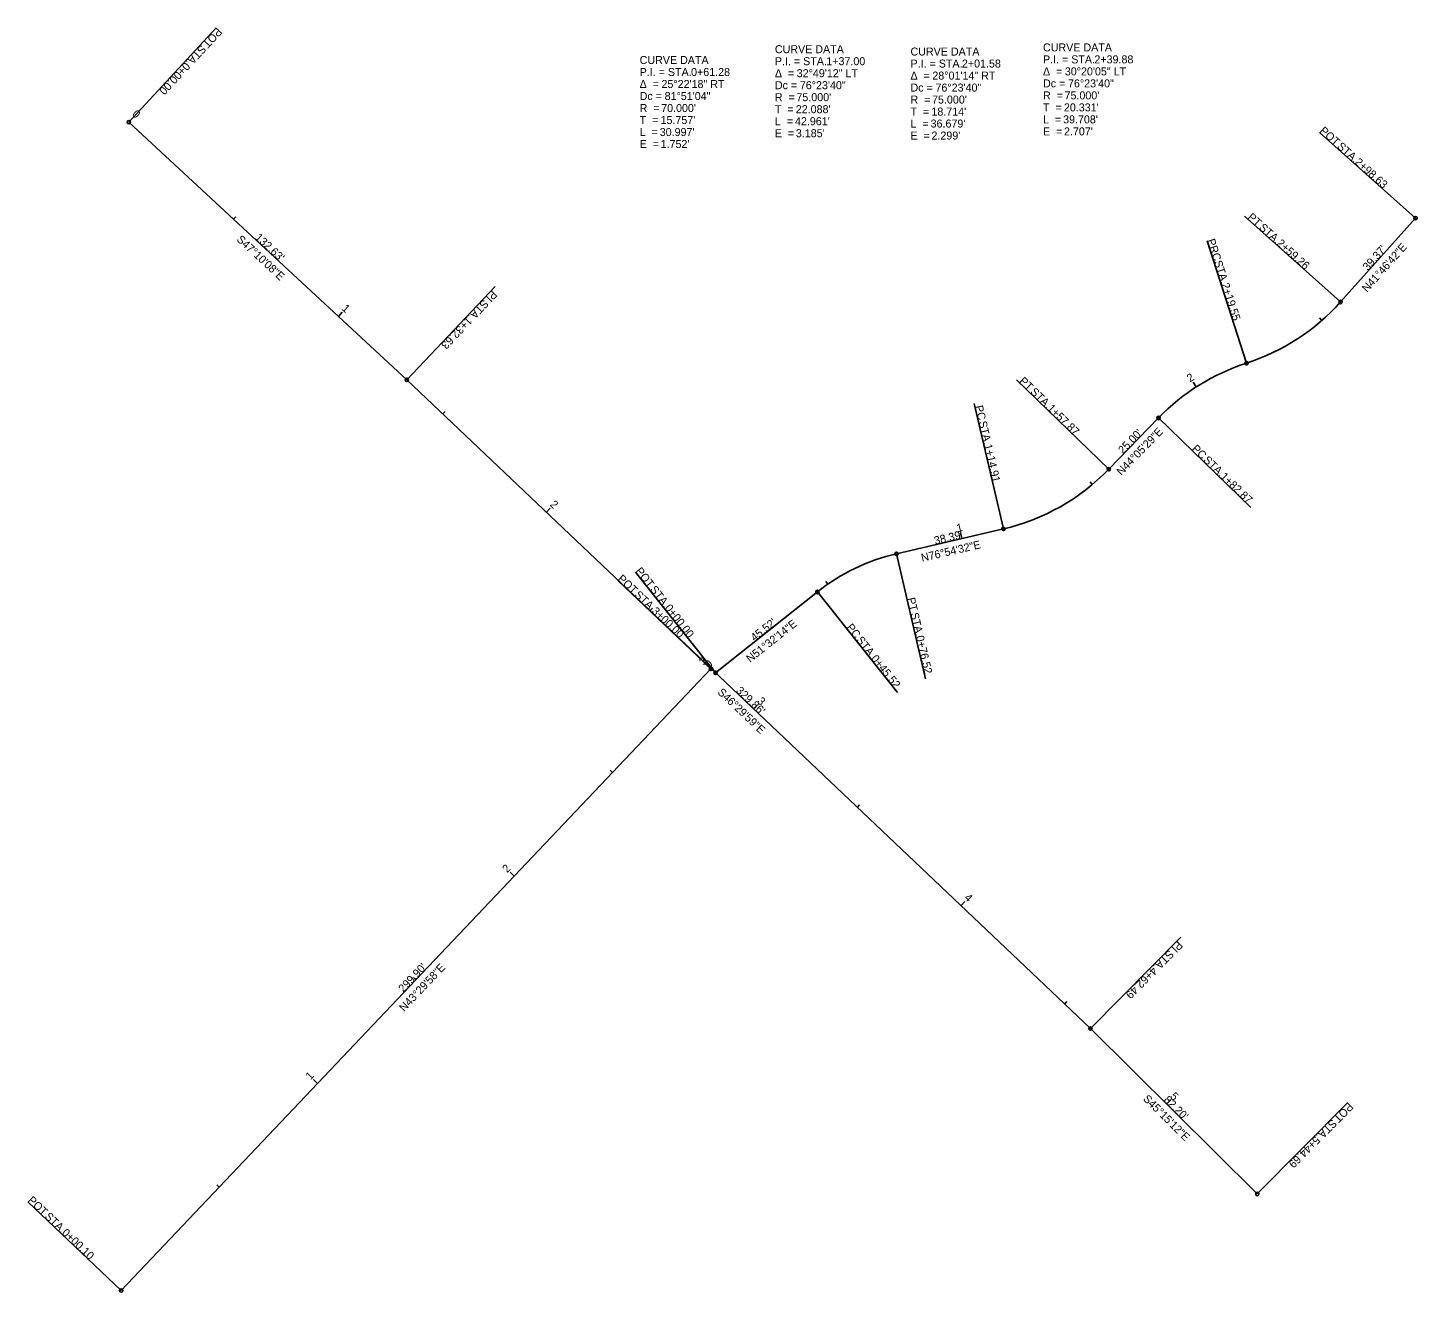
# Model space of a CAD drawing. Extents: x 1481215 to 1481995, y 378012 to 378683.
# Drawn here: x 1481214.6 to 1481700.9, y 378012.5 to 378455 of the extents above; entities that cross this region are included whole.
import ezdxf

# ---------------------------------------------------------------- set-up
doc = ezdxf.new("R2010")
doc.units = 0
for name, color, linetype in [('DT_X_Break_Line', 7, 'Continuous'), ('DT_X_Contour_Major', 7, 'Continuous'), ('DT_X_Island', 7, 'Continuous'), ('DT_X_Spot_Elev', 7, 'Continuous'), ('DT_X_Triangles', 7, 'Continuous'), ('DT_X_Void', 7, 'Continuous')]:
    doc.layers.add(name, color=color, linetype=linetype)

msp = doc.modelspace()

# ---------------------------------------------------------------- linework, layer by layer
at = {"layer": 'DT_X_Break_Line'}
for p, q in [((1481250.01, 378421.95), (1481251.37, 378423.41)), ((1481286.68, 378387.96), (1481287.5, 378388.84)), ((1481323.35, 378353.96), (1481324.71, 378355.43)), ((1481667.5, 378352.51), (1481666.71, 378353.42)), ((1481623.57, 378329.26), (1481622.48, 378330.94)), ((1481359.88, 378319.82), (1481360.7, 378320.69)), ((1481587.19, 378295.11), (1481586.42, 378296.03)), ((1481396.15, 378285.41), (1481397.52, 378286.86)), ((1481541.55, 378276.22), (1481541.1, 378278.17)), ((1481494.59, 378260.21), (1481493.9, 378261.19)), ((1481432.41, 378250.99), (1481433.24, 378251.86)), ((1481453.74, 378230.61), (1481452.29, 378231.99)), ((1481455.35, 378229.22), (1481454.11, 378230.79)), ((1481468.68, 378216.57), (1481470.06, 378218.02)), ((1481419.33, 378194.34), (1481418.46, 378195.17)), ((1481504.95, 378182.15), (1481505.78, 378183.02)), ((1481384.91, 378158.07), (1481383.46, 378159.45)), ((1481541.22, 378147.73), (1481542.6, 378149.18)), ((1481350.49, 378121.8), (1481349.62, 378122.63)), ((1481577.49, 378113.32), (1481578.31, 378114.19)), ((1481316.07, 378085.54), (1481314.62, 378086.91)), ((1481613.19, 378078.31), (1481614.6, 378079.73)), ((1481281.66, 378049.27), (1481280.79, 378050.09))]:
    msp.add_line(p, q, dxfattribs=at)
at = {"layer": 'DT_X_Spot_Elev'}
for p, q in [((1481250.01, 378421.95), (1481280.61, 378454.95)), ((1481700.31, 378388.38), (1481666.75, 378418.36)), ((1481674.08, 378359.02), (1481640.52, 378389)), ((1481641.18, 378337.61), (1481627.36, 378380.44)), ((1481347.28, 378331.78), (1481378.26, 378364.42)), ((1481592.96, 378300.47), (1481560.64, 378331.78)), ((1481556.08, 378279.6), (1481545.88, 378323.43)), ((1481610.35, 378318.42), (1481642.67, 378287.11)), ((1481518.68, 378270.9), (1481528.87, 378227.07)), ((1481455.35, 378229.22), (1481427.36, 378264.46)), ((1481453.74, 378230.61), (1481421.1, 378261.59)), ((1481490.99, 378257.53), (1481518.98, 378222.3)), ((1481586.55, 378104.72), (1481618.23, 378136.68)), ((1481644.93, 378046.85), (1481676.61, 378078.81)), ((1481247.31, 378013.07), (1481214.66, 378044.04))]:
    msp.add_line(p, q, dxfattribs=at)
for centre in [(1481250.01, 378421.95), (1481700.31, 378388.38), (1481674.08, 378359.02), (1481641.18, 378337.61), (1481347.28, 378331.78), (1481610.35, 378318.42), (1481592.96, 378300.47), (1481556.08, 378279.6), (1481518.68, 378270.9), (1481490.99, 378257.53), (1481453.74, 378230.61), (1481455.35, 378229.22), (1481586.55, 378104.72), (1481644.93, 378046.85), (1481247.31, 378013.07)]:
    msp.add_circle(centre, 0.6, dxfattribs=at)
at = {"layer": 'DT_X_Triangles'}
for p, q in [((1481250.01, 378421.95), (1481347.28, 378331.78)), ((1481674.08, 378359.02), (1481700.31, 378388.38)), ((1481347.28, 378331.78), (1481586.55, 378104.72)), ((1481592.96, 378300.47), (1481610.35, 378318.42)), ((1481518.68, 378270.9), (1481556.08, 378279.6)), ((1481455.35, 378229.22), (1481490.99, 378257.53)), ((1481247.31, 378013.07), (1481453.74, 378230.61)), ((1481586.55, 378104.72), (1481644.93, 378046.85))]:
    msp.add_line(p, q, dxfattribs=at)
for centre, radius, start, end in [((1481618.15, 378408.99), 75, 287.8864, 318.2211), ((1481664.22, 378266.24), 75, 107.8883, 135.909), ((1481539.09, 378352.65), 75, 283.0911, 315.9112), ((1481534.53, 378202.72), 70, 103.0911, 128.4628)]:
    msp.add_arc(centre, radius, start, end, dxfattribs=at)

# ---------------------------------------------------------------- texts
at = {"layer": 'DT_X_Break_Line'}
for s, rotation, p in [('0', 317.169, (1481250.95, 378424.48)), ('1', 317.169, (1481324.32, 378356.47)), ('2', 32.823, (1481621.39, 378330.84)), ('2', 316.4996, (1481397.16, 378287.89)), ('1', 13.0911, (1481540.02, 378278.43)), ('3', 46.5006, (1481451.27, 378231.63)), ('0', 38.4628, (1481452.99, 378230.54)), ('3', 316.4996, (1481469.71, 378219.05)), ('2', 46.5006, (1481382.42, 378159.09)), ('4', 316.4996, (1481542.18, 378150.27)), ('1', 46.5006, (1481313.58, 378086.54)), ('5', 315.2533, (1481614.26, 378080.77))]:
    msp.add_text(s, height=2.8, rotation=rotation, dxfattribs=at).set_placement(p)
at = {"layer": 'DT_X_Contour_Major'}
for s, rotation, p in [('S47°10\'08"E', 317.169, (1481287.53, 378380.62)), ('N41°46\'42"E', 48.2217, (1481683.36, 378362.21)), ('N44°05\'29"E', 45.9086, (1481597.37, 378298.12)), ('N76°54\'32"E', 13.0911, (1481527.64, 378268.06)), ('N51°32\'14"E', 38.4628, (1481467.45, 378232.7)), ('S46°29\'59"E', 316.4996, (1481455.84, 378222.14)), ('N43°29\'58"E', 46.5006, (1481346.35, 378110.47)), ('S45°15\'12"E', 315.2533, (1481604.76, 378079.91))]:
    msp.add_text(s, height=2.8, rotation=rotation, dxfattribs=at).set_placement(p)
at = {"layer": 'DT_X_Island'}
for s, p in [('CURVE DATA', (1481476.11, 378446.08)), ('CURVE DATA', (1481523.57, 378445.25)), ('CURVE DATA', (1481569.94, 378446.71)), ('CURVE DATA', (1481428.78, 378442.29)), ('P.I. = STA. ', (1481476.11, 378441.88)), ('1+37.00', (1481494.1, 378441.88)), ('P.I. = STA. ', (1481523.57, 378441.05)), ('2+01.58', (1481541.56, 378441.05)), ('P.I. = STA. ', (1481569.94, 378442.51)), ('2+39.88', (1481587.93, 378442.51)), ('P.I. = STA. ', (1481428.78, 378438.09)), ('0+61.28', (1481446.77, 378438.09)), ('Δ  = ', (1481476.11, 378437.68)), ('32°49\'12" LT', (1481483.75, 378437.68)), ('Δ  = ', (1481523.57, 378436.85)), ('28°01\'14" RT', (1481531.22, 378436.85)), ('Δ  = ', (1481569.94, 378438.31)), ('30°20\'05" LT', (1481577.59, 378438.31)), ('Δ  = ', (1481428.78, 378433.89)), ('25°22\'18" RT', (1481436.42, 378433.89)), ('Dc = ', (1481476.11, 378433.48)), ('76°23\'40"', (1481484.85, 378433.48)), ('Dc = ', (1481523.57, 378432.65)), ('76°23\'40"', (1481532.31, 378432.65)), ('Dc = ', (1481569.94, 378434.11)), ('76°23\'40"', (1481578.69, 378434.11)), ('Dc = ', (1481428.78, 378429.69)), ('R  = ', (1481428.78, 378425.49)), ("70.000'", (1481436.31, 378425.49)), ('81°51\'04"', (1481437.52, 378429.69)), ('R  = ', (1481476.11, 378429.28)), ("75.000'", (1481483.64, 378429.28)), ('R  = ', (1481523.57, 378428.45)), ("75.000'", (1481531.11, 378428.45)), ('T  = ', (1481569.94, 378425.71)), ('R  = ', (1481569.94, 378429.91)), ("20.331'", (1481577.26, 378425.71)), ("75.000'", (1481577.48, 378429.91)), ('T  = ', (1481428.78, 378421.29)), ("15.757'", (1481436.09, 378421.29)), ('T  = ', (1481476.11, 378425.08)), ('L  = ', (1481476.11, 378420.88)), ("42.961'", (1481483.14, 378420.88)), ("22.088'", (1481483.42, 378425.08)), ('T  = ', (1481523.57, 378424.25)), ("18.714'", (1481530.89, 378424.25)), ('L  = ', (1481569.94, 378421.51)), ("39.708'", (1481576.98, 378421.51)), ('L  = ', (1481428.78, 378417.09)), ("30.997'", (1481435.81, 378417.09)), ('E  = ', (1481476.11, 378416.68)), ("3.185'", (1481483.45, 378416.68)), ('L  = ', (1481523.57, 378420.05)), ('E  = ', (1481523.57, 378415.85)), ("36.679'", (1481530.61, 378420.05)), ("2.299'", (1481530.91, 378415.85)), ('E  = ', (1481569.94, 378417.31)), ("2.707'", (1481577.29, 378417.31)), ('E  = ', (1481428.78, 378412.89)), ("1.752'", (1481436.12, 378412.89))]:
    msp.add_text(s, height=2.8, dxfattribs=at).set_placement(p)
at = {"layer": 'DT_X_Spot_Elev'}
for s, rotation, p in [('POT', 227.169, (1481280.88, 378455.19)), (' STA. ', 227.169, (1481276.03, 378449.96)), ('0+00.00', 227.169, (1481269.7, 378443.13)), ('POT', 318.2217, (1481666.55, 378418.58)), (' STA. ', 318.2217, (1481671.87, 378413.83)), ('2+98.63', 318.2217, (1481678.82, 378407.62)), ('PT', 318.2217, (1481641.31, 378388.34)), (' STA. ', 318.2217, (1481644.56, 378385.44)), ('PRC', 287.8864, (1481627.34, 378380.63)), ('2+59.26', 318.2217, (1481651.51, 378379.23)), (' STA. ', 287.8864, (1481629.46, 378374.06)), ('2+19.55', 287.8864, (1481632.32, 378365.19)), (' STA. ', 226.4996, (1481374.89, 378360.82)), ('PI', 226.4996, (1481377.17, 378363.23)), ('1+32.63', 226.4996, (1481368.47, 378354.06)), ('PT', 315.9086, (1481561.41, 378331.08)), (' STA. ', 315.9086, (1481564.54, 378328.05)), ('PC', 283.0911, (1481546.13, 378322.52)), ('1+57.87', 315.9086, (1481571.24, 378321.56)), (' STA. ', 283.0911, (1481547.17, 378318.04)), ('1+14.91', 283.0911, (1481549.29, 378308.96)), ('PC', 315.909, (1481621.81, 378307.37)), (' STA. ', 315.909, (1481625.12, 378304.17)), ('1+82.87', 315.909, (1481631.81, 378297.68)), ('POT', 316.5006, (1481420.86, 378261.87)), ('POT', 308.4628, (1481427.16, 378264.77)), (' STA. ', 316.5006, (1481426.03, 378256.96)), (' STA. ', 308.4628, (1481431.6, 378259.18)), ('0+00.00', 308.4628, (1481437.4, 378251.88)), ('PT', 283.0911, (1481522.36, 378255.25)), ('3+00.00', 316.5006, (1481432.8, 378250.54)), (' STA. ', 283.0911, (1481523.34, 378251.01)), ('PC', 308.4628, (1481500.95, 378245.07)), (' STA. ', 308.4628, (1481503.81, 378241.46)), ('0+76.52', 283.0911, (1481525.45, 378241.93)), ('0+45.52', 308.4628, (1481509.61, 378234.16)), (' STA. ', 225.2533, (1481614.81, 378133.17)), ('PI', 225.2533, (1481617.14, 378135.53)), ('4+62.49', 225.2533, (1481608.25, 378126.55)), ('POT', 225.2533, (1481676.87, 378079.01)), (' STA. ', 225.2533, (1481671.85, 378073.95)), ('5+44.69', 225.2533, (1481665.28, 378067.33)), ('POT', 316.5006, (1481214.42, 378044.32)), (' STA. ', 316.5006, (1481219.59, 378039.41)), ('0+00.10', 316.5006, (1481226.36, 378033))]:
    msp.add_text(s, height=2.8, rotation=rotation, dxfattribs=at).set_placement(p)
at = {"layer": 'DT_X_Void'}
for s, rotation, p in [("132.63'", 317.169, (1481293.95, 378381.27)), ("39.37'", 48.2217, (1481683.62, 378369.76)), ("25.00'", 45.9086, (1481597.93, 378305.65)), ("38.39'", 13.0911, (1481532.19, 378274.08)), ("45.52'", 38.4628, (1481468.98, 378240.1)), ("329.86'", 316.4996, (1481462.27, 378222.71)), ("299.90'", 46.5006, (1481346.07, 378117.19)), ("82.20'", 315.2533, (1481611.99, 378079.55))]:
    msp.add_text(s, height=2.8, rotation=rotation, dxfattribs=at).set_placement(p)

doc.saveas('drawing.dxf')
